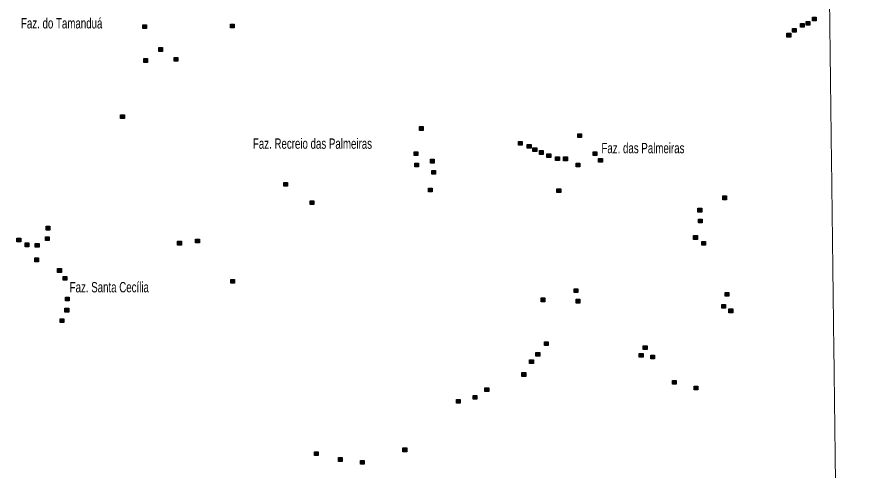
# Model space of a CAD drawing. Extents: x 265.7 to 292.1, y 7676.2 to 7704.2.
# Drawn here: x 285.57 to 292.1, y 7693.69 to 7697.19 of the extents above; entities that cross this region are included whole.
import ezdxf

# ---------------------------------------------------------------- set-up
doc = ezdxf.new("R2010")
doc.units = 0
doc.header["$LTSCALE"] = 0.032
doc.layers.add('2', color=7, linetype='Continuous', lineweight=25)
doc.layers.add('63', color=7, linetype='Continuous', lineweight=13)
doc.layers.add('61', color=7, linetype='Continuous')

msp = doc.modelspace()

# ---------------------------------------------------------------- hatches: boundary and pattern name
at = {"layer": '2'}
for points in [[(286.5391, 7697.133), (286.5681, 7697.133), (286.5681, 7697.104), (286.5391, 7697.104)], [(287.217, 7697.137), (287.246, 7697.137), (287.246, 7697.108), (287.217, 7697.108)], [(291.6186, 7697.142), (291.6476, 7697.142), (291.6476, 7697.113), (291.6186, 7697.113)], [(291.6621, 7697.1572), (291.6911, 7697.1572), (291.6911, 7697.1282), (291.6621, 7697.1282)], [(291.7115, 7697.192), (291.7405, 7697.192), (291.7405, 7697.163), (291.7115, 7697.163)], [(291.5145, 7697.0668), (291.5435, 7697.0668), (291.5435, 7697.0378), (291.5145, 7697.0378)], [(291.557, 7697.1031), (291.586, 7697.1031), (291.586, 7697.0741), (291.557, 7697.0741)], [(286.6626, 7696.9555), (286.6916, 7696.9555), (286.6916, 7696.9265), (286.6626, 7696.9265)], [(286.5463, 7696.8708), (286.5753, 7696.8708), (286.5753, 7696.8418), (286.5463, 7696.8418)], [(286.7821, 7696.8797), (286.8111, 7696.8797), (286.8111, 7696.8507), (286.7821, 7696.8507)], [(286.3679, 7696.4374), (286.3969, 7696.4374), (286.3969, 7696.4084), (286.3679, 7696.4084)], [(288.6769, 7696.3454), (288.7059, 7696.3454), (288.7059, 7696.3164), (288.6769, 7696.3164)], [(289.898, 7696.2889), (289.927, 7696.2889), (289.927, 7696.2599), (289.898, 7696.2599)], [(289.4413, 7696.2315), (289.4703, 7696.2315), (289.4703, 7696.2025), (289.4413, 7696.2025)], [(289.5089, 7696.2074), (289.5379, 7696.2074), (289.5379, 7696.1784), (289.5089, 7696.1784)], [(289.5526, 7696.1823), (289.5816, 7696.1823), (289.5816, 7696.1533), (289.5526, 7696.1533)], [(289.6027, 7696.1597), (289.6317, 7696.1597), (289.6317, 7696.1307), (289.6027, 7696.1307)], [(288.6349, 7696.1501), (288.6639, 7696.1501), (288.6639, 7696.1211), (288.6349, 7696.1211)], [(288.7601, 7696.0927), (288.7891, 7696.0927), (288.7891, 7696.0637), (288.7601, 7696.0637)], [(289.6608, 7696.1347), (289.6898, 7696.1347), (289.6898, 7696.1057), (289.6608, 7696.1057)], [(289.7277, 7696.113), (289.7567, 7696.113), (289.7567, 7696.084), (289.7277, 7696.084)], [(289.7898, 7696.1105), (289.8188, 7696.1105), (289.8188, 7696.0815), (289.7898, 7696.0815)], [(290.0166, 7696.15), (290.0456, 7696.15), (290.0456, 7696.121), (290.0166, 7696.121)], [(290.0595, 7696.1), (290.0885, 7696.1), (290.0885, 7696.071), (290.0595, 7696.071)], [(288.6398, 7696.0628), (288.6688, 7696.0628), (288.6688, 7696.0338), (288.6398, 7696.0338)], [(289.8851, 7696.0629), (289.9141, 7696.0629), (289.9141, 7696.0339), (289.8851, 7696.0339)], [(288.7705, 7696.0072), (288.7995, 7696.0072), (288.7995, 7695.9782), (288.7705, 7695.9782)], [(287.6278, 7695.9128), (287.6568, 7695.9128), (287.6568, 7695.8838), (287.6278, 7695.8838)], [(288.7454, 7695.8708), (288.7744, 7695.8708), (288.7744, 7695.8418), (288.7454, 7695.8418)], [(289.7382, 7695.8644), (289.7672, 7695.8644), (289.7672, 7695.8354), (289.7382, 7695.8354)], [(287.8319, 7695.7724), (287.8609, 7695.7724), (287.8609, 7695.7434), (287.8319, 7695.7434)], [(291.0182, 7695.8095), (291.0472, 7695.8095), (291.0472, 7695.7805), (291.0182, 7695.7805)], [(290.8269, 7695.7142), (290.8559, 7695.7142), (290.8559, 7695.6852), (290.8269, 7695.6852)], [(290.8302, 7695.6295), (290.8592, 7695.6295), (290.8592, 7695.6005), (290.8302, 7695.6005)], [(285.7933, 7695.5747), (285.8223, 7695.5747), (285.8223, 7695.5457), (285.7933, 7695.5457)], [(290.7937, 7695.5027), (290.8227, 7695.5027), (290.8227, 7695.4737), (290.7937, 7695.4737)], [(285.5673, 7695.4826), (285.5963, 7695.4826), (285.5963, 7695.4536), (285.5673, 7695.4536)], [(285.6303, 7695.4463), (285.6593, 7695.4463), (285.6593, 7695.4173), (285.6303, 7695.4173)], [(285.7094, 7695.4414), (285.7384, 7695.4414), (285.7384, 7695.4124), (285.7094, 7695.4124)], [(285.7869, 7695.4932), (285.8159, 7695.4932), (285.8159, 7695.4642), (285.7869, 7695.4642)], [(286.8087, 7695.4588), (286.8377, 7695.4588), (286.8377, 7695.4298), (286.8087, 7695.4298)], [(286.9473, 7695.4754), (286.9763, 7695.4754), (286.9763, 7695.4464), (286.9473, 7695.4464)], [(290.8568, 7695.4568), (290.8858, 7695.4568), (290.8858, 7695.4278), (290.8568, 7695.4278)], [(285.7062, 7695.3301), (285.7352, 7695.3301), (285.7352, 7695.3011), (285.7062, 7695.3011)], [(285.8813, 7695.2478), (285.9103, 7695.2478), (285.9103, 7695.2188), (285.8813, 7695.2188)], [(285.9249, 7695.1864), (285.9539, 7695.1864), (285.9539, 7695.1574), (285.9249, 7695.1574)], [(287.2194, 7695.1638), (287.2484, 7695.1638), (287.2484, 7695.1348), (287.2194, 7695.1348)], [(289.8713, 7695.0911), (289.9003, 7695.0911), (289.9003, 7695.0621), (289.8713, 7695.0621)], [(291.0375, 7695.0638), (291.0665, 7695.0638), (291.0665, 7695.0348), (291.0375, 7695.0348)], [(285.9427, 7695.0283), (285.9717, 7695.0283), (285.9717, 7694.9993), (285.9427, 7694.9993)], [(289.6155, 7695.021), (289.6445, 7695.021), (289.6445, 7694.992), (289.6155, 7694.992)], [(289.8859, 7695.0104), (289.9149, 7695.0104), (289.9149, 7694.9814), (289.8859, 7694.9814)], [(285.9385, 7694.9412), (285.9675, 7694.9412), (285.9675, 7694.9122), (285.9385, 7694.9122)], [(291.0116, 7694.9709), (291.0406, 7694.9709), (291.0406, 7694.9419), (291.0116, 7694.9419)], [(291.0665, 7694.9362), (291.0955, 7694.9362), (291.0955, 7694.9072), (291.0665, 7694.9072)], [(285.9015, 7694.8597), (285.9305, 7694.8597), (285.9305, 7694.8307), (285.9015, 7694.8307)], [(289.6413, 7694.6813), (289.6703, 7694.6813), (289.6703, 7694.6523), (289.6413, 7694.6523)], [(290.4046, 7694.6518), (290.4336, 7694.6518), (290.4336, 7694.6228), (290.4046, 7694.6228)], [(289.576, 7694.6005), (289.605, 7694.6005), (289.605, 7694.5715), (289.576, 7694.5715)], [(290.3741, 7694.5924), (290.4031, 7694.5924), (290.4031, 7694.5634), (290.3741, 7694.5634)], [(289.5268, 7694.5432), (289.5558, 7694.5432), (289.5558, 7694.5142), (289.5268, 7694.5142)], [(290.4629, 7694.5796), (290.4919, 7694.5796), (290.4919, 7694.5506), (290.4629, 7694.5506)], [(289.4679, 7694.4439), (289.4969, 7694.4439), (289.4969, 7694.4149), (289.4679, 7694.4149)], [(289.1821, 7694.327), (289.2111, 7694.327), (289.2111, 7694.298), (289.1821, 7694.298)], [(290.6307, 7694.3842), (290.6597, 7694.3842), (290.6597, 7694.3552), (290.6307, 7694.3552)], [(290.797, 7694.3398), (290.826, 7694.3398), (290.826, 7694.3108), (290.797, 7694.3108)], [(289.0902, 7694.268), (289.1192, 7694.268), (289.1192, 7694.239), (289.0902, 7694.239)], [(288.9626, 7694.2366), (288.9916, 7694.2366), (288.9916, 7694.2076), (288.9626, 7694.2076)], [(287.8659, 7693.8322), (287.8949, 7693.8322), (287.8949, 7693.8032), (287.8659, 7693.8032)], [(288.5486, 7693.8613), (288.5776, 7693.8613), (288.5776, 7693.8323), (288.5486, 7693.8323)], [(288.0506, 7693.7869), (288.0796, 7693.7869), (288.0796, 7693.7579), (288.0506, 7693.7579)], [(288.2202, 7693.7651), (288.2492, 7693.7651), (288.2492, 7693.7361), (288.2202, 7693.7361)]]:
    msp.add_hatch(color=256, dxfattribs=at).paths.add_polyline_path(points)

# ---------------------------------------------------------------- linework, layer by layer
for points in [[(286.5391, 7697.133), (286.5681, 7697.133), (286.5681, 7697.104), (286.5391, 7697.104)], [(287.217, 7697.137), (287.246, 7697.137), (287.246, 7697.108), (287.217, 7697.108)], [(291.6186, 7697.142), (291.6476, 7697.142), (291.6476, 7697.113), (291.6186, 7697.113)], [(291.6621, 7697.1572), (291.6911, 7697.1572), (291.6911, 7697.1282), (291.6621, 7697.1282)], [(291.7115, 7697.192), (291.7405, 7697.192), (291.7405, 7697.163), (291.7115, 7697.163)], [(291.5145, 7697.0668), (291.5435, 7697.0668), (291.5435, 7697.0378), (291.5145, 7697.0378)], [(291.557, 7697.1031), (291.586, 7697.1031), (291.586, 7697.0741), (291.557, 7697.0741)], [(286.6626, 7696.9555), (286.6916, 7696.9555), (286.6916, 7696.9265), (286.6626, 7696.9265)], [(286.5463, 7696.8708), (286.5753, 7696.8708), (286.5753, 7696.8418), (286.5463, 7696.8418)], [(286.7821, 7696.8797), (286.8111, 7696.8797), (286.8111, 7696.8507), (286.7821, 7696.8507)], [(286.3679, 7696.4374), (286.3969, 7696.4374), (286.3969, 7696.4084), (286.3679, 7696.4084)], [(288.6769, 7696.3454), (288.7059, 7696.3454), (288.7059, 7696.3164), (288.6769, 7696.3164)], [(289.898, 7696.2889), (289.927, 7696.2889), (289.927, 7696.2599), (289.898, 7696.2599)], [(289.4413, 7696.2315), (289.4703, 7696.2315), (289.4703, 7696.2025), (289.4413, 7696.2025)], [(289.5089, 7696.2074), (289.5379, 7696.2074), (289.5379, 7696.1784), (289.5089, 7696.1784)], [(289.5526, 7696.1823), (289.5816, 7696.1823), (289.5816, 7696.1533), (289.5526, 7696.1533)], [(289.6027, 7696.1597), (289.6317, 7696.1597), (289.6317, 7696.1307), (289.6027, 7696.1307)], [(288.6349, 7696.1501), (288.6639, 7696.1501), (288.6639, 7696.1211), (288.6349, 7696.1211)], [(288.7601, 7696.0927), (288.7891, 7696.0927), (288.7891, 7696.0637), (288.7601, 7696.0637)], [(289.6608, 7696.1347), (289.6898, 7696.1347), (289.6898, 7696.1057), (289.6608, 7696.1057)], [(289.7277, 7696.113), (289.7567, 7696.113), (289.7567, 7696.084), (289.7277, 7696.084)], [(289.7898, 7696.1105), (289.8188, 7696.1105), (289.8188, 7696.0815), (289.7898, 7696.0815)], [(290.0166, 7696.15), (290.0456, 7696.15), (290.0456, 7696.121), (290.0166, 7696.121)], [(290.0595, 7696.1), (290.0885, 7696.1), (290.0885, 7696.071), (290.0595, 7696.071)], [(288.6398, 7696.0628), (288.6688, 7696.0628), (288.6688, 7696.0338), (288.6398, 7696.0338)], [(289.8851, 7696.0629), (289.9141, 7696.0629), (289.9141, 7696.0339), (289.8851, 7696.0339)], [(288.7705, 7696.0072), (288.7995, 7696.0072), (288.7995, 7695.9782), (288.7705, 7695.9782)], [(287.6278, 7695.9128), (287.6568, 7695.9128), (287.6568, 7695.8838), (287.6278, 7695.8838)], [(288.7454, 7695.8708), (288.7744, 7695.8708), (288.7744, 7695.8418), (288.7454, 7695.8418)], [(289.7382, 7695.8644), (289.7672, 7695.8644), (289.7672, 7695.8354), (289.7382, 7695.8354)], [(287.8319, 7695.7724), (287.8609, 7695.7724), (287.8609, 7695.7434), (287.8319, 7695.7434)], [(291.0182, 7695.8095), (291.0472, 7695.8095), (291.0472, 7695.7805), (291.0182, 7695.7805)], [(290.8269, 7695.7142), (290.8559, 7695.7142), (290.8559, 7695.6852), (290.8269, 7695.6852)], [(290.8302, 7695.6295), (290.8592, 7695.6295), (290.8592, 7695.6005), (290.8302, 7695.6005)], [(285.7933, 7695.5747), (285.8223, 7695.5747), (285.8223, 7695.5457), (285.7933, 7695.5457)], [(290.7937, 7695.5027), (290.8227, 7695.5027), (290.8227, 7695.4737), (290.7937, 7695.4737)], [(285.5673, 7695.4826), (285.5963, 7695.4826), (285.5963, 7695.4536), (285.5673, 7695.4536)], [(285.6303, 7695.4463), (285.6593, 7695.4463), (285.6593, 7695.4173), (285.6303, 7695.4173)], [(285.7094, 7695.4414), (285.7384, 7695.4414), (285.7384, 7695.4124), (285.7094, 7695.4124)], [(285.7869, 7695.4932), (285.8159, 7695.4932), (285.8159, 7695.4642), (285.7869, 7695.4642)], [(286.8087, 7695.4588), (286.8377, 7695.4588), (286.8377, 7695.4298), (286.8087, 7695.4298)], [(286.9473, 7695.4754), (286.9763, 7695.4754), (286.9763, 7695.4464), (286.9473, 7695.4464)], [(290.8568, 7695.4568), (290.8858, 7695.4568), (290.8858, 7695.4278), (290.8568, 7695.4278)], [(285.7062, 7695.3301), (285.7352, 7695.3301), (285.7352, 7695.3011), (285.7062, 7695.3011)], [(285.8813, 7695.2478), (285.9103, 7695.2478), (285.9103, 7695.2188), (285.8813, 7695.2188)], [(285.9249, 7695.1864), (285.9539, 7695.1864), (285.9539, 7695.1574), (285.9249, 7695.1574)], [(287.2194, 7695.1638), (287.2484, 7695.1638), (287.2484, 7695.1348), (287.2194, 7695.1348)], [(289.8713, 7695.0911), (289.9003, 7695.0911), (289.9003, 7695.0621), (289.8713, 7695.0621)], [(291.0375, 7695.0638), (291.0665, 7695.0638), (291.0665, 7695.0348), (291.0375, 7695.0348)], [(285.9427, 7695.0283), (285.9717, 7695.0283), (285.9717, 7694.9993), (285.9427, 7694.9993)], [(289.6155, 7695.021), (289.6445, 7695.021), (289.6445, 7694.992), (289.6155, 7694.992)], [(289.8859, 7695.0104), (289.9149, 7695.0104), (289.9149, 7694.9814), (289.8859, 7694.9814)], [(285.9385, 7694.9412), (285.9675, 7694.9412), (285.9675, 7694.9122), (285.9385, 7694.9122)], [(291.0116, 7694.9709), (291.0406, 7694.9709), (291.0406, 7694.9419), (291.0116, 7694.9419)], [(291.0665, 7694.9362), (291.0955, 7694.9362), (291.0955, 7694.9072), (291.0665, 7694.9072)], [(285.9015, 7694.8597), (285.9305, 7694.8597), (285.9305, 7694.8307), (285.9015, 7694.8307)], [(289.6413, 7694.6813), (289.6703, 7694.6813), (289.6703, 7694.6523), (289.6413, 7694.6523)], [(290.4046, 7694.6518), (290.4336, 7694.6518), (290.4336, 7694.6228), (290.4046, 7694.6228)], [(289.576, 7694.6005), (289.605, 7694.6005), (289.605, 7694.5715), (289.576, 7694.5715)], [(290.3741, 7694.5924), (290.4031, 7694.5924), (290.4031, 7694.5634), (290.3741, 7694.5634)], [(289.5268, 7694.5432), (289.5558, 7694.5432), (289.5558, 7694.5142), (289.5268, 7694.5142)], [(290.4629, 7694.5796), (290.4919, 7694.5796), (290.4919, 7694.5506), (290.4629, 7694.5506)], [(289.4679, 7694.4439), (289.4969, 7694.4439), (289.4969, 7694.4149), (289.4679, 7694.4149)], [(289.1821, 7694.327), (289.2111, 7694.327), (289.2111, 7694.298), (289.1821, 7694.298)], [(290.6307, 7694.3842), (290.6597, 7694.3842), (290.6597, 7694.3552), (290.6307, 7694.3552)], [(290.797, 7694.3398), (290.826, 7694.3398), (290.826, 7694.3108), (290.797, 7694.3108)], [(289.0902, 7694.268), (289.1192, 7694.268), (289.1192, 7694.239), (289.0902, 7694.239)], [(288.9626, 7694.2366), (288.9916, 7694.2366), (288.9916, 7694.2076), (288.9626, 7694.2076)], [(287.8659, 7693.8322), (287.8949, 7693.8322), (287.8949, 7693.8032), (287.8659, 7693.8032)], [(288.5486, 7693.8613), (288.5776, 7693.8613), (288.5776, 7693.8323), (288.5486, 7693.8323)], [(288.0506, 7693.7869), (288.0796, 7693.7869), (288.0796, 7693.7579), (288.0506, 7693.7579)], [(288.2202, 7693.7651), (288.2492, 7693.7651), (288.2492, 7693.7361), (288.2202, 7693.7361)]]:
    msp.add_lwpolyline(points, close=True, dxfattribs=at)
at = {"layer": '63'}
msp.add_spline([(292.1022, 7676.5221), (292.0951, 7677.087), (292.088, 7677.6519), (292.081, 7678.2168), (292.0739, 7678.7818), (292.0668, 7679.3467), (292.0598, 7679.9116), (292.0527, 7680.4765), (292.0457, 7681.0414), (292.0386, 7681.6064), (292.0316, 7682.1713), (292.0245, 7682.7362), (292.0175, 7683.3011), (292.0104, 7683.866), (292.0034, 7684.431), (291.9963, 7684.9959), (291.9893, 7685.5608), (291.9822, 7686.1257), (291.9752, 7686.6906), (291.9681, 7687.2556), (291.9611, 7687.8205), (291.9541, 7688.3854), (291.947, 7688.9503), (291.94, 7689.5152), (291.933, 7690.0801), (291.9259, 7690.6451), (291.9189, 7691.21), (291.9119, 7691.7749), (291.9049, 7692.3398), (291.8978, 7692.9047), (291.8908, 7693.4696), (291.8838, 7694.0345), (291.8768, 7694.5995), (291.8698, 7695.1644), (291.8628, 7695.7293), (291.8557, 7696.2942), (291.8487, 7696.8591), (291.8417, 7697.424), (291.8347, 7697.9889), (291.8277, 7698.5539), (291.8207, 7699.1188), (291.8137, 7699.6837), (291.8067, 7700.2486), (291.7997, 7700.8135), (291.7927, 7701.3784), (291.7857, 7701.9433), (291.7787, 7702.5082), (291.7717, 7703.0731), (291.7647, 7703.638), (291.7577, 7704.203)], degree=3, dxfattribs=at)

# ---------------------------------------------------------------- texts
at = {"layer": '61', "width": 0.7}
for s, p in [('Faz. do Tamanduá', (285.5988, 7697.1041)), ('Faz. Recreio das Palmeiras', (287.3899, 7696.1741)), ('Faz. das Palmeiras', (290.0817, 7696.1394)), ('Faz. Santa Cecília', (285.9747, 7695.0641))]:
    msp.add_text(s, height=0.08, dxfattribs=at).set_placement(p)

doc.saveas('drawing.dxf')
